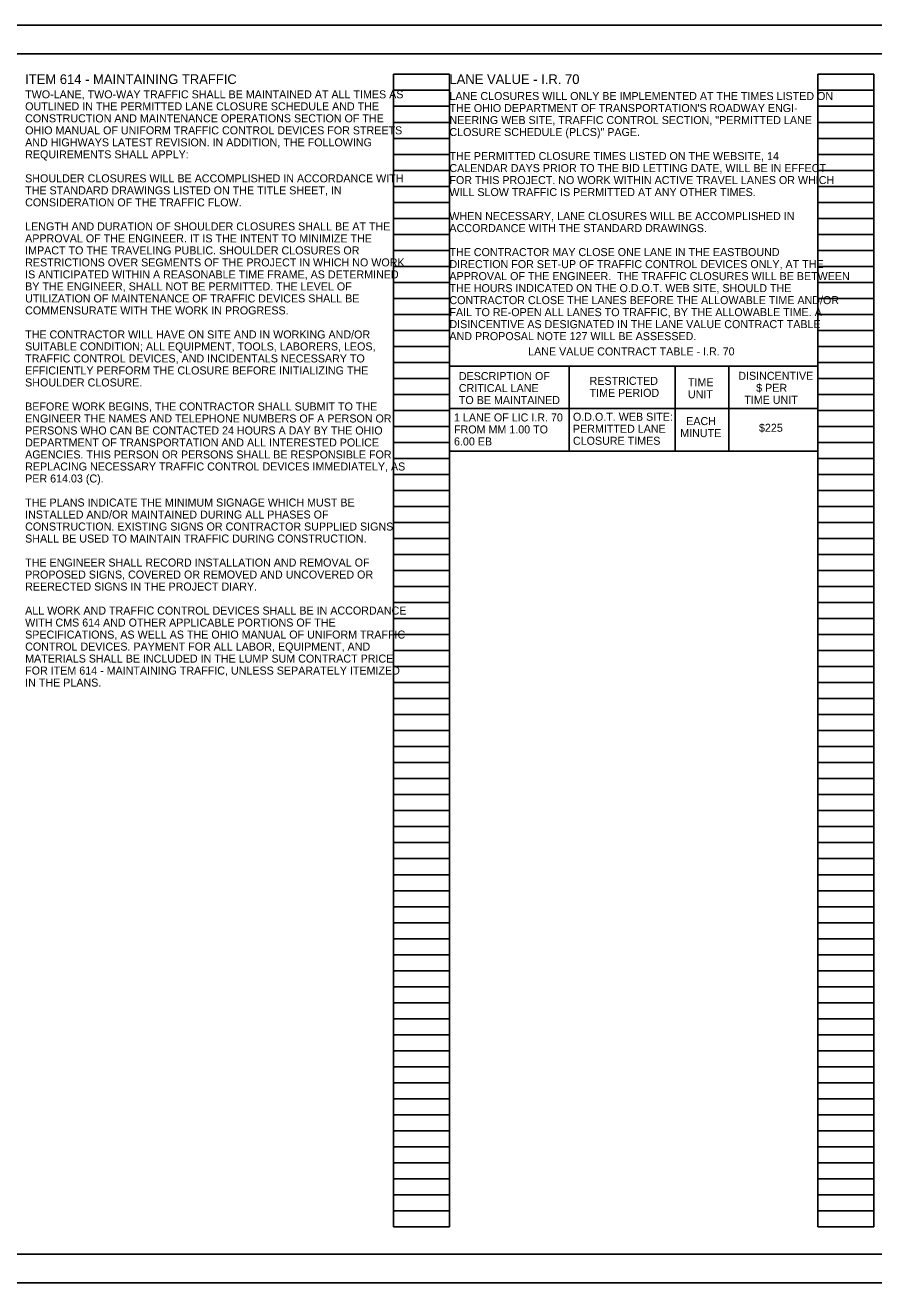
# Model space of a CAD drawing. Extents: x -7.8 to 41.7, y 0 to 22.
# Drawn here: x 2.4 to 17.24, y 0 to 22 of the extents above; entities that cross this region are included whole.
import ezdxf

# ---------------------------------------------------------------- set-up
doc = ezdxf.new("R2010")
doc.units = 0
for name, color, linetype in [('Default', 7, 'Continuous'), ('SH_Border', 7, 'Continuous'), ('SH_Cut_Line', 7, 'Continuous'), ('SH_Data', 7, 'Continuous'), ('SH_Text', 7, 'Continuous')]:
    doc.layers.add(name, color=color, linetype=linetype)

msp = doc.modelspace()

# ---------------------------------------------------------------- linework, layer by layer
at = {"layer": 'SH_Border'}
msp.add_lwpolyline([(1.5, 21.5), (33.5, 21.5), (33.5, 0.5), (1.5, 0.5)], close=True, dxfattribs=at)
at = {"layer": 'SH_Cut_Line'}
msp.add_lwpolyline([(0, 0), (34, 0), (34, 22), (0, 22)], close=True, dxfattribs=at)
at = {"layer": 'SH_Data'}
for p, q in [((8.84, 0.98), (8.84, 21.14)), ((8.84, 21.14), (9.82, 21.14)), ((9.82, 0.98), (9.82, 21.14)), ((16.26, 0.98), (16.26, 21.14)), ((16.26, 21.14), (17.24, 21.14)), ((17.24, 0.98), (17.24, 21.14)), ((8.84, 20.86), (9.82, 20.86)), ((16.26, 20.86), (17.24, 20.86)), ((8.84, 20.58), (9.82, 20.58)), ((16.26, 20.58), (17.24, 20.58)), ((8.84, 20.3), (9.82, 20.3)), ((16.26, 20.3), (17.24, 20.3)), ((8.84, 20.02), (9.82, 20.02)), ((16.26, 20.02), (17.24, 20.02)), ((8.84, 19.74), (9.82, 19.74)), ((16.26, 19.74), (17.24, 19.74)), ((8.84, 19.46), (9.82, 19.46)), ((16.26, 19.46), (17.24, 19.46)), ((8.84, 19.18), (9.82, 19.18)), ((16.26, 19.18), (17.24, 19.18)), ((8.84, 18.9), (9.82, 18.9)), ((16.26, 18.9), (17.24, 18.9)), ((8.84, 18.62), (9.82, 18.62)), ((16.26, 18.62), (17.24, 18.62)), ((8.84, 18.34), (9.82, 18.34)), ((16.26, 18.34), (17.24, 18.34)), ((8.84, 18.06), (9.82, 18.06)), ((16.26, 18.06), (17.24, 18.06)), ((8.84, 17.78), (9.82, 17.78)), ((16.26, 17.78), (17.24, 17.78)), ((8.84, 17.5), (9.82, 17.5)), ((16.26, 17.5), (17.24, 17.5)), ((8.84, 17.22), (9.82, 17.22)), ((16.26, 17.22), (17.24, 17.22)), ((8.84, 16.94), (9.82, 16.94)), ((16.26, 16.94), (17.24, 16.94)), ((8.84, 16.66), (9.82, 16.66)), ((16.26, 16.66), (17.24, 16.66)), ((8.84, 16.38), (9.82, 16.38)), ((16.26, 16.38), (17.24, 16.38)), ((8.84, 16.1), (9.82, 16.1)), ((16.26, 16.1), (17.24, 16.1)), ((8.84, 15.82), (9.82, 15.82)), ((16.26, 15.82), (17.24, 15.82)), ((8.84, 15.54), (9.82, 15.54)), ((16.26, 15.54), (17.24, 15.54)), ((8.84, 15.26), (9.82, 15.26)), ((16.26, 15.26), (17.24, 15.26)), ((8.84, 14.98), (9.82, 14.98)), ((16.26, 14.98), (17.24, 14.98)), ((8.84, 14.7), (9.82, 14.7)), ((16.26, 14.7), (17.24, 14.7)), ((8.84, 14.42), (9.82, 14.42)), ((16.26, 14.42), (17.24, 14.42)), ((8.84, 14.14), (9.82, 14.14)), ((16.26, 14.14), (17.24, 14.14)), ((8.84, 13.86), (9.82, 13.86)), ((16.26, 13.86), (17.24, 13.86)), ((8.84, 13.58), (9.82, 13.58)), ((16.26, 13.58), (17.24, 13.58)), ((8.84, 13.3), (9.82, 13.3)), ((16.26, 13.3), (17.24, 13.3)), ((8.84, 13.02), (9.82, 13.02)), ((16.26, 13.02), (17.24, 13.02)), ((8.84, 12.74), (9.82, 12.74)), ((16.26, 12.74), (17.24, 12.74)), ((8.84, 12.46), (9.82, 12.46)), ((16.26, 12.46), (17.24, 12.46)), ((8.84, 12.18), (9.82, 12.18)), ((16.26, 12.18), (17.24, 12.18)), ((8.84, 11.9), (9.82, 11.9)), ((16.26, 11.9), (17.24, 11.9)), ((8.84, 11.62), (9.82, 11.62)), ((16.26, 11.62), (17.24, 11.62)), ((8.84, 11.34), (9.82, 11.34)), ((16.26, 11.34), (17.24, 11.34)), ((8.84, 11.06), (9.82, 11.06)), ((16.26, 11.06), (17.24, 11.06)), ((8.84, 10.78), (9.82, 10.78)), ((16.26, 10.78), (17.24, 10.78)), ((8.84, 10.5), (9.82, 10.5)), ((16.26, 10.5), (17.24, 10.5)), ((8.84, 10.22), (9.82, 10.22)), ((16.26, 10.22), (17.24, 10.22)), ((8.84, 9.94), (9.82, 9.94)), ((16.26, 9.94), (17.24, 9.94)), ((8.84, 9.66), (9.82, 9.66)), ((16.26, 9.66), (17.24, 9.66)), ((8.84, 9.38), (9.82, 9.38)), ((16.26, 9.38), (17.24, 9.38)), ((8.84, 9.1), (9.82, 9.1)), ((16.26, 9.1), (17.24, 9.1)), ((8.84, 8.82), (9.82, 8.82)), ((16.26, 8.82), (17.24, 8.82)), ((8.84, 8.54), (9.82, 8.54)), ((16.26, 8.54), (17.24, 8.54)), ((8.84, 8.26), (9.82, 8.26)), ((16.26, 8.26), (17.24, 8.26)), ((8.84, 7.98), (9.82, 7.98)), ((16.26, 7.98), (17.24, 7.98)), ((8.84, 7.7), (9.82, 7.7)), ((16.26, 7.7), (17.24, 7.7)), ((8.84, 7.42), (9.82, 7.42)), ((16.26, 7.42), (17.24, 7.42)), ((8.84, 7.14), (9.82, 7.14)), ((16.26, 7.14), (17.24, 7.14)), ((8.84, 6.86), (9.82, 6.86)), ((16.26, 6.86), (17.24, 6.86)), ((8.84, 6.58), (9.82, 6.58)), ((16.26, 6.58), (17.24, 6.58)), ((8.84, 6.3), (9.82, 6.3)), ((16.26, 6.3), (17.24, 6.3)), ((8.84, 6.02), (9.82, 6.02)), ((16.26, 6.02), (17.24, 6.02)), ((8.84, 5.74), (9.82, 5.74)), ((16.26, 5.74), (17.24, 5.74)), ((8.84, 5.46), (9.82, 5.46)), ((16.26, 5.46), (17.24, 5.46)), ((8.84, 5.18), (9.82, 5.18)), ((16.26, 5.18), (17.24, 5.18)), ((8.84, 4.9), (9.82, 4.9)), ((16.26, 4.9), (17.24, 4.9)), ((8.84, 4.62), (9.82, 4.62)), ((16.26, 4.62), (17.24, 4.62)), ((8.84, 4.34), (9.82, 4.34)), ((16.26, 4.34), (17.24, 4.34)), ((8.84, 4.06), (9.82, 4.06)), ((16.26, 4.06), (17.24, 4.06)), ((8.84, 3.78), (9.82, 3.78)), ((16.26, 3.78), (17.24, 3.78)), ((8.84, 3.5), (9.82, 3.5)), ((16.26, 3.5), (17.24, 3.5)), ((8.84, 3.22), (9.82, 3.22)), ((16.26, 3.22), (17.24, 3.22)), ((8.84, 2.94), (9.82, 2.94)), ((16.26, 2.94), (17.24, 2.94)), ((8.84, 2.66), (9.82, 2.66)), ((16.26, 2.66), (17.24, 2.66)), ((8.84, 2.38), (9.82, 2.38)), ((16.26, 2.38), (17.24, 2.38)), ((8.84, 2.1), (9.82, 2.1)), ((16.26, 2.1), (17.24, 2.1)), ((8.84, 1.82), (9.82, 1.82)), ((16.26, 1.82), (17.24, 1.82)), ((8.84, 1.54), (9.82, 1.54)), ((16.26, 1.54), (17.24, 1.54)), ((8.84, 1.26), (9.82, 1.26)), ((16.26, 1.26), (17.24, 1.26)), ((8.84, 0.98), (9.82, 0.98)), ((16.26, 0.98), (17.24, 0.98))]:
    msp.add_line(p, q, dxfattribs=at)
at = {"layer": 'SH_Text'}
for p, q in [((11.914, 14.549), (11.914, 16.033)), ((13.766, 14.549), (13.766, 16.033)), ((14.705, 14.549), (14.705, 16.033)), ((9.82, 15.295), (16.26, 15.295))]:
    msp.add_line(p, q, dxfattribs=at)
msp.add_lwpolyline([(9.82, 16.033), (16.26, 16.033), (16.26, 14.549), (9.82, 14.549)], close=True, dxfattribs=at)

# ---------------------------------------------------------------- texts
at = {"layer": 'Default'}
for s, height, p in [('ITEM 614 - MAINTAINING TRAFFIC', 0.17, (2.4, 20.97)), ('TWO-LANE, TWO-WAY TRAFFIC SHALL BE MAINTAINED AT ALL TIMES AS ', 0.14, (2.4, 20.72)), ('OUTLINED IN THE PERMITTED LANE CLOSURE SCHEDULE AND THE ', 0.14, (2.4, 20.51)), ('CONSTRUCTION AND MAINTENANCE OPERATIONS SECTION OF THE ', 0.14, (2.4, 20.3)), ('AND HIGHWAYS LATEST REVISION. IN ADDITION, THE FOLLOWING ', 0.14, (2.4, 19.88)), ('OHIO MANUAL OF UNIFORM TRAFFIC CONTROL DEVICES FOR STREETS ', 0.14, (2.4, 20.09)), ('REQUIREMENTS SHALL APPLY:', 0.14, (2.4, 19.67)), ('SHOULDER CLOSURES WILL BE ACCOMPLISHED IN ACCORDANCE WITH ', 0.14, (2.4, 19.25)), ('THE STANDARD DRAWINGS LISTED ON THE TITLE SHEET, IN ', 0.14, (2.4, 19.04)), ('CONSIDERATION OF THE TRAFFIC FLOW.', 0.14, (2.4, 18.83)), ('LENGTH AND DURATION OF SHOULDER CLOSURES SHALL BE AT THE ', 0.14, (2.4, 18.41)), ('APPROVAL OF THE ENGINEER. IT IS THE INTENT TO MINIMIZE THE ', 0.14, (2.4, 18.2)), ('IMPACT TO THE TRAVELING PUBLIC. SHOULDER CLOSURES OR ', 0.14, (2.4, 17.99)), ('RESTRICTIONS OVER SEGMENTS OF THE PROJECT IN WHICH NO WORK ', 0.14, (2.4, 17.78)), ('IS ANTICIPATED WITHIN A REASONABLE TIME FRAME, AS DETERMINED ', 0.14, (2.4, 17.57)), ('BY THE ENGINEER, SHALL NOT BE PERMITTED. THE LEVEL OF ', 0.14, (2.4, 17.36)), ('UTILIZATION OF MAINTENANCE OF TRAFFIC DEVICES SHALL BE ', 0.14, (2.4, 17.15)), ('COMMENSURATE WITH THE WORK IN PROGRESS.', 0.14, (2.4, 16.94)), ('THE CONTRACTOR WILL HAVE ON SITE AND IN WORKING AND/OR ', 0.14, (2.4, 16.52)), ('SUITABLE CONDITION; ALL EQUIPMENT, TOOLS, LABORERS, LEOS, ', 0.14, (2.4, 16.31)), ('TRAFFIC CONTROL DEVICES, AND INCIDENTALS NECESSARY TO ', 0.14, (2.4, 16.1)), ('EFFICIENTLY PERFORM THE CLOSURE BEFORE INITIALIZING THE ', 0.14, (2.4, 15.89)), ('SHOULDER CLOSURE.', 0.14, (2.4, 15.68)), ('BEFORE WORK BEGINS, THE CONTRACTOR SHALL SUBMIT TO THE ', 0.14, (2.4, 15.26)), ('ENGINEER THE NAMES AND TELEPHONE NUMBERS OF A PERSON OR ', 0.14, (2.4, 15.05)), ('PERSONS WHO CAN BE CONTACTED 24 HOURS A DAY BY THE OHIO ', 0.14, (2.4, 14.84)), ('DEPARTMENT OF TRANSPORTATION AND ALL INTERESTED POLICE ', 0.14, (2.4, 14.63)), ('AGENCIES. THIS PERSON OR PERSONS SHALL BE RESPONSIBLE FOR ', 0.14, (2.4, 14.42)), ('REPLACING NECESSARY TRAFFIC CONTROL DEVICES IMMEDIATELY, AS ', 0.14, (2.4, 14.21)), ('PER 614.03 (C).', 0.14, (2.4, 14)), ('THE PLANS INDICATE THE MINIMUM SIGNAGE WHICH MUST BE ', 0.14, (2.4, 13.58)), ('INSTALLED AND/OR MAINTAINED DURING ALL PHASES OF ', 0.14, (2.4, 13.37)), ('CONSTRUCTION. EXISTING SIGNS OR CONTRACTOR SUPPLIED SIGNS ', 0.14, (2.4, 13.16)), ('SHALL BE USED TO MAINTAIN TRAFFIC DURING CONSTRUCTION.', 0.14, (2.4, 12.95)), ('THE ENGINEER SHALL RECORD INSTALLATION AND REMOVAL OF ', 0.14, (2.4, 12.53)), ('PROPOSED SIGNS, COVERED OR REMOVED AND UNCOVERED OR ', 0.14, (2.4, 12.32)), ('REERECTED SIGNS IN THE PROJECT DIARY.', 0.14, (2.4, 12.11)), ('ALL WORK AND TRAFFIC CONTROL DEVICES SHALL BE IN ACCORDANCE ', 0.14, (2.4, 11.69)), ('WITH CMS 614 AND OTHER APPLICABLE PORTIONS OF THE ', 0.14, (2.4, 11.48)), ('SPECIFICATIONS, AS WELL AS THE OHIO MANUAL OF UNIFORM TRAFFIC ', 0.14, (2.4, 11.27)), ('CONTROL DEVICES. PAYMENT FOR ALL LABOR, EQUIPMENT, AND ', 0.14, (2.4, 11.06)), ('MATERIALS SHALL BE INCLUDED IN THE LUMP SUM CONTRACT PRICE ', 0.14, (2.4, 10.85)), ('FOR ITEM 614 - MAINTAINING TRAFFIC, UNLESS SEPARATELY ITEMIZED ', 0.14, (2.4, 10.64)), ('IN THE PLANS.', 0.14, (2.4, 10.43))]:
    msp.add_text(s, height=height, dxfattribs=at).set_placement(p)
at = {"layer": 'SH_Text'}
for s, height, p in [('LANE VALUE - I.R. 70', 0.17, (9.82, 20.97)), ('LANE CLOSURES WILL ONLY BE IMPLEMENTED AT THE TIMES LISTED ON ', 0.14, (9.82, 20.69)), ("THE OHIO DEPARTMENT OF TRANSPORTATION'S ROADWAY ENGI-", 0.14, (9.82, 20.48)), ('NEERING WEB SITE, TRAFFIC CONTROL SECTION, "PERMITTED LANE ', 0.14, (9.82, 20.27)), ('CLOSURE SCHEDULE (PLCS)" PAGE.', 0.14, (9.82, 20.06)), ('THE PERMITTED CLOSURE TIMES LISTED ON THE WEBSITE, 14 ', 0.14, (9.82, 19.64)), ('CALENDAR DAYS PRIOR TO THE BID LETTING DATE, WILL BE IN EFFECT ', 0.14, (9.82, 19.43)), ('FOR THIS PROJECT. NO WORK WITHIN ACTIVE TRAVEL LANES OR WHICH ', 0.14, (9.82, 19.22)), ('WILL SLOW TRAFFIC IS PERMITTED AT ANY OTHER TIMES.', 0.14, (9.82, 19.01)), ('WHEN NECESSARY, LANE CLOSURES WILL BE ACCOMPLISHED IN ', 0.14, (9.82, 18.59)), ('ACCORDANCE WITH THE STANDARD DRAWINGS.  ', 0.14, (9.82, 18.38)), ('THE CONTRACTOR MAY CLOSE ONE LANE IN THE EASTBOUND ', 0.14, (9.82, 17.96)), ('DIRECTION FOR SET-UP OF TRAFFIC CONTROL DEVICES ONLY, AT THE', 0.14, (9.82, 17.75)), ('APPROVAL OF THE ENGINEER.  THE TRAFFIC CLOSURES WILL BE BETWEEN', 0.14, (9.82, 17.54)), ('THE HOURS INDICATED ON THE O.D.O.T. WEB SITE, SHOULD THE', 0.14, (9.82, 17.33)), ('CONTRACTOR CLOSE THE LANES BEFORE THE ALLOWABLE TIME AND/OR', 0.14, (9.82, 17.12)), ('FAIL TO RE-OPEN ALL LANES TO TRAFFIC, BY THE ALLOWABLE TIME. A', 0.14, (9.82, 16.91)), ('DISINCENTIVE AS DESIGNATED IN THE LANE VALUE CONTRACT TABLE', 0.14, (9.82, 16.7)), ('AND PROPOSAL NOTE 127 WILL BE ASSESSED.  ', 0.14, (9.82, 16.49)), ('LANE VALUE CONTRACT TABLE - I.R. 70', 0.14, (11.197, 16.223)), ('DESCRIPTION OF ', 0.14, (9.985, 15.792)), ('RESTRICTED ', 0.14, (12.271, 15.708)), ('DISINCENTIVE', 0.14, (14.872, 15.796)), ('CRITICAL LANE', 0.14, (9.985, 15.582)), ('TIME PERIOD', 0.14, (12.271, 15.498)), ('TIME ', 0.14, (13.991, 15.684)), ('      $ PER ', 0.14, (14.872, 15.586)), ('TO BE MAINTAINED', 0.14, (9.985, 15.372)), ('UNIT', 0.14, (13.991, 15.474)), ('  TIME UNIT', 0.14, (14.872, 15.376)), ('1 LANE OF LIC I.R. 70', 0.14, (9.9, 15.068)), ('O.D.O.T. WEB SITE:', 0.14, (11.98, 15.08)), ('FROM MM 1.00 TO ', 0.14, (9.9, 14.858)), ('PERMITTED LANE ', 0.14, (11.98, 14.87)), ('  EACH', 0.14, (13.857, 15.004)), ('$225', 0.14, (15.233, 14.887)), ('6.00 EB', 0.14, (9.9, 14.648)), ('CLOSURE TIMES', 0.14, (11.98, 14.66)), ('MINUTE', 0.14, (13.857, 14.794))]:
    msp.add_text(s, height=height, dxfattribs=at).set_placement(p)

doc.saveas('drawing.dxf')
